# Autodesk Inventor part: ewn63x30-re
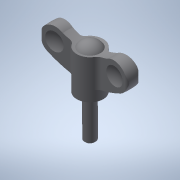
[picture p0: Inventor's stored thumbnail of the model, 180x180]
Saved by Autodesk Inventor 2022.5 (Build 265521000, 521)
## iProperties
Created: 2017-05
Part Number: ewn63x30-re
Material: 一般
Document SubType Name: Modeling
Designer: imaocorp
Density: 1 g/cm^3
Appearance: 既定
Author: imaocorp
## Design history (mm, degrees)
node "ewn63x30-re.x_t1"
node "ewn63x30-re"
node "Base1"
